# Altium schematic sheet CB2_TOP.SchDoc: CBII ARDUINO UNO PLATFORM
size A3; Engineer: SHOWELL; DocumentNumber: 1; Revision: 1.00; SheetNumber: 1; SheetTotal: 1; PageSetup: Record=PageOptions|CenterHorizontal=True|CenterVertical=True|PrintScale=1.47|XCorrection=1.00|YCorrection=1.00|PrintKind=0|BorderSize=5000000|LeftOffset=0|BottomOffset=0|Orientation=2|PaperLength=1000|PaperWidth=1000|Scale=100|PaperSource=7|PrintQuality=-4|MediaType=1|DitherType=10|PaperKind=A2|PrintScaleMode=1
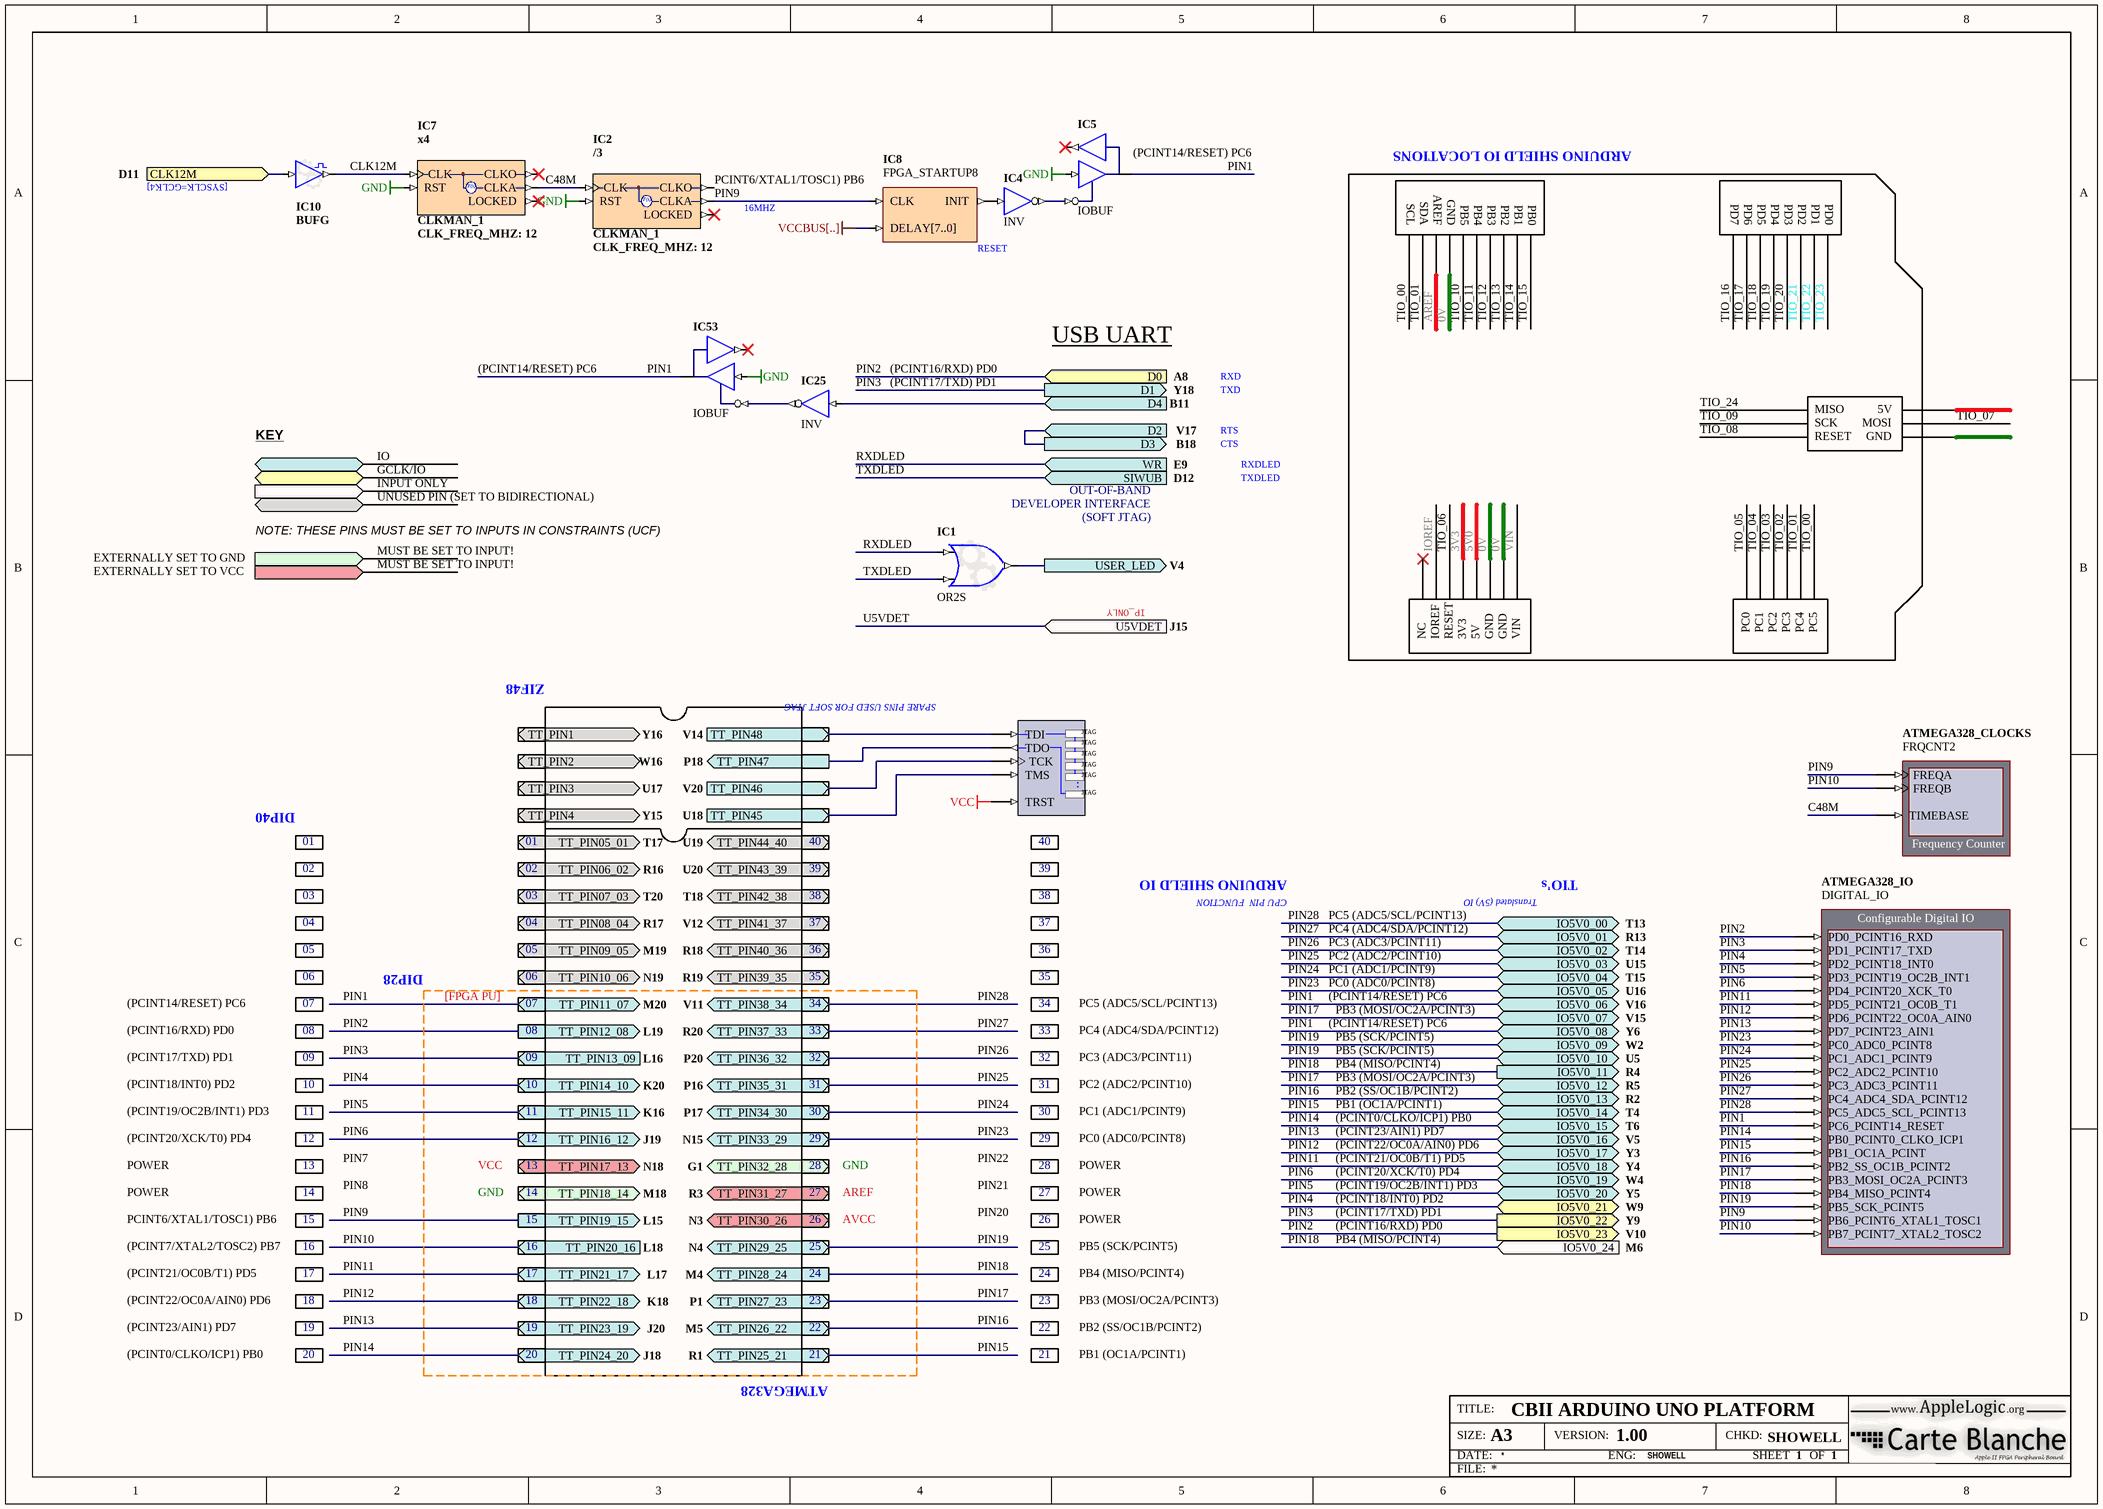
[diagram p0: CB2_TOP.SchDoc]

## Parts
ATMEGA328_CLOCKS  FRQCNT2
ATMEGA328_IO  DIGITAL_IO
IC1  OR2S
IC2  CLKMAN_1  CLK_FREQ_MHZ: 12  ClkA_Operation: /3
IC4  INV
IC5  IOBUF
IC7  CLKMAN_1  CLK_FREQ_MHZ: 12  ClkA_Operation: x4
IC8  FPGA_STARTUP8
IC10  BUFG
IC25  INV
IC53  IOBUF
NEXUS_JTAG_PORT  NEXUS_JTAG_PORT  (value not drawn)

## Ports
CLK12M (in, see D11), D0 (in, see A8), D1 (out, see Y18), D2 (in, see V17), D3 (out, see B18), D4 (in, see B11), IO5V0_00 (bidir, see T13), IO5V0_01 (bidir, see R13), IO5V0_02 (bidir, see T14), IO5V0_03 (bidir, see U15), IO5V0_04 (bidir, see T15), IO5V0_05 (bidir, see U16), IO5V0_06 (bidir, see V16), IO5V0_07 (bidir, see V15), IO5V0_08 (bidir, see Y6), IO5V0_09 (bidir, see W2), IO5V0_10 (bidir, see U5), IO5V0_11 (out, see R4), IO5V0_12 (bidir, see R5), IO5V0_13 (bidir, see R2), IO5V0_14 (bidir, see T4), IO5V0_15 (bidir, see T6), IO5V0_16 (bidir, see V5), IO5V0_17 (bidir, see Y3), IO5V0_18 (bidir, see Y4), IO5V0_19 (bidir, see W4), IO5V0_20 (bidir, see Y5), IO5V0_21 (bidir, see W9), IO5V0_22 (out, see Y9), IO5V0_23 (out, see V10), IO5V0_24 (in, see M6), SIWUB (in, see D12), TT_PIN1 (bidir, see Y16), TT_PIN2 (bidir, see W16), TT_PIN3 (bidir, see U17), TT_PIN4 (bidir, see Y15), TT_PIN05_01 (bidir, see T17), TT_PIN06_02 (bidir, see R16), TT_PIN07_03 (bidir, see T20), TT_PIN08_04 (bidir, see R17), TT_PIN09_05 (bidir, see M19), TT_PIN10_06 (bidir, see N19), TT_PIN11_07 (bidir, see M20), TT_PIN12_08 (out, see L19), TT_PIN13_09 (in, see L16), TT_PIN14_10 (bidir, see K20), TT_PIN15_11 (bidir, see K16), TT_PIN16_12 (bidir, see J19), TT_PIN17_13 (in, see N18), TT_PIN18_14 (in, see M18), TT_PIN19_15 (out, see L15), TT_PIN20_16 (in, see L18), TT_PIN21_17 (bidir, see L17), TT_PIN22_18 (bidir, see K18), TT_PIN23_19 (bidir, see J20), TT_PIN24_20 (bidir, see J18), TT_PIN25_21 (bidir, see R1), TT_PIN26_22 (bidir, see M5), TT_PIN27_23 (bidir, see P1), TT_PIN28_24 (out, see M4), TT_PIN29_25 (bidir, see N4), TT_PIN30_26 (in, see N3), TT_PIN31_27 (in, see R3), TT_PIN32_28 (in, see G1), TT_PIN33_29 (bidir, see N15), TT_PIN34_30 (bidir, see P17), TT_PIN35_31 (bidir, see P16), TT_PIN36_32 (bidir, see P20), TT_PIN37_33 (bidir, see R20), TT_PIN38_34 (bidir, see V11), TT_PIN39_35 (bidir, see R19), TT_PIN40_36 (bidir, see R18), TT_PIN41_37 (bidir, see V12), TT_PIN42_38 (bidir, see T18), TT_PIN43_39 (bidir, see U20), TT_PIN44_40 (bidir, see U19), TT_PIN45 (in, see U18), TT_PIN46 (in, see V20), TT_PIN47 (out, see P18), TT_PIN48 (in, see V14), U5VDET (in, see J15), USER_LED (out, see V4), WR (in, see E9)

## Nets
GND: IC2.RST IC5.I IC7.RST IC53.I
VCC: NEXUS_JTAG_PORT.TRST
C48M: ATMEGA328_CLOCKS.TIMEBASE IC2.CLK IC7.CLKA
CLK12M: IC7.CLK IC10.O
CLK12M: IC10.I ; port CLK12M  [a separate net that carries the same name]
D2: port D3, port D2
D4: IC25.I ; port D4
PIN1: ATMEGA328_IO.PC6_PCINT14_RESET IC5.IO IC53.IO ; port TT_PIN11_07, port IO5V0_06, port IO5V0_08
PIN2: ATMEGA328_IO.PD0_PCINT16_RXD ; port TT_PIN12_08, port IO5V0_23, port D0
PIN3: ATMEGA328_IO.PD1_PCINT17_TXD ; port TT_PIN13_09, port IO5V0_22, port D1
PIN4: ATMEGA328_IO.PD2_PCINT18_INT0 ; port TT_PIN14_10, port IO5V0_21
PIN5: ATMEGA328_IO.PD3_PCINT19_OC2B_INT1 ; port TT_PIN15_11, port IO5V0_20
PIN6: ATMEGA328_IO.PD4_PCINT20_XCK_T0 ; port TT_PIN16_12, port IO5V0_19
PIN9: ATMEGA328_CLOCKS.FREQA ATMEGA328_IO.PB6_PCINT6_XTAL1_TOSC1 IC2.CLKA IC8.CLK ; port TT_PIN19_15
PIN10: ATMEGA328_CLOCKS.FREQB ATMEGA328_IO.PB7_PCINT7_XTAL2_TOSC2 ; port TT_PIN20_16
PIN11: ATMEGA328_IO.PD5_PCINT21_OC0B_T1 ; port TT_PIN21_17, port IO5V0_18
PIN12: ATMEGA328_IO.PD6_PCINT22_OC0A_AIN0 ; port TT_PIN22_18, port IO5V0_17
PIN13: ATMEGA328_IO.PD7_PCINT23_AIN1 ; port TT_PIN23_19, port IO5V0_16
PIN14: ATMEGA328_IO.PB0_PCINT0_CLKO_ICP1 ; port TT_PIN24_20, port IO5V0_15
PIN15: ATMEGA328_IO.PB1_OC1A_PCINT ; port TT_PIN25_21, port IO5V0_14
PIN16: ATMEGA328_IO.PB2_SS_OC1B_PCINT2 ; port TT_PIN26_22, port IO5V0_13
PIN17: ATMEGA328_IO.PB3_MOSI_OC2A_PCINT3 ; port TT_PIN27_23, port IO5V0_12, port IO5V0_07
PIN18: ATMEGA328_IO.PB4_MISO_PCINT4 ; port TT_PIN28_24, port IO5V0_24, port IO5V0_11
PIN19: ATMEGA328_IO.PB5_SCK_PCINT5 ; port TT_PIN29_25, port IO5V0_10, port IO5V0_09
PIN23: ATMEGA328_IO.PC0_ADC0_PCINT8 ; port TT_PIN33_29, port IO5V0_05
PIN24: ATMEGA328_IO.PC1_ADC1_PCINT9 ; port TT_PIN34_30, port IO5V0_04
PIN25: ATMEGA328_IO.PC2_ADC2_PCINT10 ; port TT_PIN35_31, port IO5V0_03
PIN26: ATMEGA328_IO.PC3_ADC3_PCINT11 ; port TT_PIN36_32, port IO5V0_02
PIN27: ATMEGA328_IO.PC4_ADC4_SDA_PCINT12 ; port TT_PIN37_33, port IO5V0_01
PIN28: ATMEGA328_IO.PC5_ADC5_SCL_PCINT13 ; port TT_PIN38_34, port IO5V0_00
RXDLED: IC1.I0 ; port WR
TT_PIN45: NEXUS_JTAG_PORT.TMS ; port TT_PIN45
TT_PIN46: NEXUS_JTAG_PORT.TCK ; port TT_PIN46
TT_PIN47: NEXUS_JTAG_PORT.TDO ; port TT_PIN47
TT_PIN48: NEXUS_JTAG_PORT.TDI ; port TT_PIN48
TXDLED: IC1.I1 ; port SIWUB
USER_LED: IC1.O ; port USER_LED
NetIC4_I: IC4.I IC8.INIT
NetIC4_O: IC4.O IC5.T
NetIC25_O: IC25.O IC53.T

Not connected (* = marked no-connect by the designer): IC2 CLKO LOCKED*; IC5 O*; IC7 CLKO* LOCKED*; IC8 DELAY[7..0]; IC53 O*

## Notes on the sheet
- [SYSCLK=GCLK4]
- (near IC2) PCINT6/XTAL1/TOSC1) PB6
- (near IC5) (PCINT14/RESET) PC6
- ARDUINO SHIELD IO LOCATIONS
- (near IC2) 16MHZ
- SCL
- SDA
- AREF
- GND
- PB5
- PB4
- PB3
- PB2
- PB1
- PB0
- PD7
- PD6
- PD5
- PD4
- PD3
- PD2
- PD1
- PD0
- (near IC8) RESET
- (PCINT14/RESET) PC6
- (PCINT16/RXD) PD0
- USB UART
- RXD
- KEY
- (PCINT17/TXD) PD1
- TXD
- RTS
- CTS
- MISO
- SCK
- RESET
- MOSI
- 5V
- IO
- GCLK/IO
- INPUT ONLY
- UNUSED PIN (SET TO BIDIRECTIONAL)
- (near IC1) DEVELOPER INTERFACE
- OUT-OF-BAND
- RXDLED
- TXDLED
- EXTERNALLY SET TO GND
- EXTERNALLY SET TO VCC
- NOTE: THESE PINS MUST BE SET TO INPUTS IN CONSTRAINTS (UCF)
- MUST BE SET TO INPUT!
- (SOFT JTAG)
- IP_ONLY
- NC
- IOREF
- 3V3
- VIN
- PC0
- PC1
- PC2
- PC3
- PC4
- PC5
- ZIF48
- (near NEXUS_JTAG_PORT) SPARE PINS USED FOR SOFT JTAG
- DIP40
- 01
- 40
- (near NEXUS_JTAG_PORT) 40
- 02
- 03
- 39
- 38
- ARDUINO SHIELD IO
- CPU PIN  FUNCTION
- PC5 (ADC5/SCL/PCINT13)
- Translated (5V) IO
- TIO's
- 04
- 05
- 06
- DIP28
- 37
- 36
- 35
- PC4 (ADC4/SDA/PCINT12)
- PC3 (ADC3/PCINT11)
- PC2 (ADC2/PCINT10)
- PC1 (ADC1/PCINT9)
- PC0 (ADC0/PCINT8)
- 07
- 08
- [FPGA PU]
- 34
- 33
- PB5 (SCK/PCINT5)
- PB3 (MOSI/OC2A/PCINT3)
- (PCINT18/INT0) PD2
- (PCINT19/OC2B/INT1) PD3
- 09
- 10
- 11
- 32
- 31
- 30
- (PCINT0/CLKO/ICP1) PB0
- PB4 (MISO/PCINT4)
- PB2 (SS/OC1B/PCINT2)
- PB1 (OC1A/PCINT1)
- (PCINT20/XCK/T0) PD4
- POWER
- 12
- 13
- VCC
- 29
- 28
- (PCINT21/OC0B/T1) PD5
- (PCINT22/OC0A/AIN0) PD6
- (PCINT23/AIN1) PD7
- PCINT6/XTAL1/TOSC1) PB6
- (PCINT7/XTAL2/TOSC2) PB7
- 14
- 15
- 16
- 27
- 26
- 25
- AVCC
- 17
- 18
- 24
- 23
- 19
- 20
- 22
- 21
- ATMEGA328
- Labels drawn without touching a wire or pin: 0V, 3V3, 5V0, AREF, IOREF, PIN7, PIN8, PIN20, PIN21, PIN22, TIO_00, TIO_01, TIO_02, TIO_03, TIO_04, TIO_05, TIO_06, TIO_07, TIO_08, TIO_09, TIO_10, TIO_11, TIO_12, TIO_13, TIO_14, TIO_15, TIO_16, TIO_17, TIO_18, TIO_19, TIO_20, TIO_21, TIO_22, TIO_23, TIO_24, VCCBUS[..], VIN

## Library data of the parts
ATMEGA328_CLOCKS = FRQCNT2: Frequency Counter; NEXUS_CORE: Instrument; NEXUS_JTAG_DEVICE: True; NEXUS_JTAG_ORDER: 0
ATMEGA328_IO = DIGITAL_IO: Configurable Digital IO; NEXUS_CORE: Instrument; NEXUS_JTAG_DEVICE: True; NEXUS_JTAG_ORDER: 0; ConfigurationParameters: {}Version[2.0]{}StorageType[3]{}InterfaceType[Parallel]{}SchCompWidth[140]{}Input0Name[PD0_PCINT16_RXD]{}Input0Width[1]{}Input0InitValue[0]{}Input0Kind[LEDs]{}Input0LEDStyle[Green]{}Input1Name[PD1_PCINT17_TXD]{}Input1Width[1]{}Input1InitValue[0]{}Input1Kind[LEDs]{}Input1LEDStyle[Green]{}Input2Name[PD2_PCINT18_INT0]{}Input2Width[1]{}Input2InitValue[0]{}Input2Kind[LEDs]{}Input2LEDStyle[Green]{}Input3Name[PD3_PCINT19_OC2B_INT1]{}Input3Width[1]{}Input3InitValue[0]{}Input3Kind[LEDs]{}Input3LEDStyle[Green]{}Input4Name[PD4_PCINT20_XCK_T0]{}Input4Width[1]{}Input4InitValue[0]{}Input4Kind[LEDs]{}Input4LEDStyle[Green]{}Input5Name[PD5_PCINT21_OC0B_T1]{}Input5Width[1]{}Input5InitValue[0]{}Input5Kind[LEDs]{}Input5LEDStyle[Green]{}Input6Name[PD6_PCINT22_OC0A_AIN0]{}Input6Width[1]{}Input6InitValue[0]{}Input6Kind[LEDs]{}Input6LEDStyle[Green]{}Input7Name[PD7_PCINT23_AIN1]{}Input7Width[1]{}Input7InitValue[0]{}Input7Kind[LEDs]{}Input7LEDStyle[Green]{}Input8Name[PC0_ADC0_PCINT8]{}Input8Width[1]{}Input8InitValue[0]{}Input8Kind[LEDs]{}Input8LEDStyle[Red]{}Input9Name[PC1_ADC1_PCINT9]{}Input9Width[1]{}Input9InitValue[0]{}Input9Kind[LEDs]{}Input9LEDStyle[Red]{}Input10Name[PC2_ADC2_PCINT10]{}Input10Width[1]{}Input10InitValue[0]{}Input10Kind[LEDs]{}Input10LEDStyle[Red]{}Input11Name[PC3_ADC3_PCINT11]{}Input11Width[1]{}Input11InitValue[0]{}Input11Kind[LEDs]{}Input11LEDStyle[Red]{}Input12Name[PC4_ADC4_SDA_PCINT12]{}Input12Width[1]{}Input12InitValue[0]{}Input12Kind[LEDs]{}Input12LEDStyle[Red]{}Input13Name[PC5_ADC5_SCL_PCINT13]{}Input13Width[1]{}Input13InitValue[0]{}Input13Kind[LEDs]{}Input13LEDStyle[Red]{}Input14Name[PC6_PCINT14_RESET]{}Input14Width[1]{}Input14InitValue[0]{}Input14Kind[LEDs]{}Input14LEDStyle[Red]{}Input15Name[PB0_PCINT0_CLKO_ICP1]{}Input15Width[1]{}Input15InitValue[0]{}Input15Kind[LEDs]{}Input15LEDStyle[Blue]{}Input16Name[PB1_OC1A_PCINT]{}Input16Width[1]{}Input16InitValue[0]{}Input16Kind[LEDs]{}Input16LEDStyle[Blue]{}Input17Name[PB2_SS_OC1B_PCINT2]{}Input17Width[1]{}Input17InitValue[0]{}Input17Kind[LEDs]{}Input17LEDStyle[Blue]{}Input18Name[PB3_MOSI_OC2A_PCINT3]{}Input18Width[1]{}Input18InitValue[0]{}Input18Kind[LEDs]{}Input18LEDStyle[Blue]{}Input19Name[PB4_MISO_PCINT4]{}Input19Width[1]{}Input19InitValue[0]{}Input19Kind[LEDs]{}Input19LEDStyle[Blue]{}Input20Name[PB5_SCK_PCINT5]{}Input20Width[1]{}Input20InitValue[0]{}Input20Kind[LEDs]{}Input20LEDStyle[Blue]{}Input21Name[PB6_PCINT6_XTAL1_TOSC1]{}Input21Width[1]{}Input21InitValue[0]{}Input21Kind[LEDs]{}Input21LEDStyle[Blue]{}Input22Name[PB7_PCINT7_XTAL2_TOSC2]{}Input22Width[1]{}Input22InitValue[0]{}Input22Kind[LEDs]{}Input22LEDStyle[Blue]{}NoOutputs[ ]{}Designator[ATMEGA328_IO]{}InternalID[1]{}
IC1 = GATE: Configurable Generic Gate; ConfiguratorName: GENERIC_GATE; ConfigurationParameters: {}Version[1.1]{}GateKind[OR]{}BusInput[False]{}GateInputType[Bit]{}GateOutputOption[Normal]{}BusWidth[8]{}RegisterOutputs[False]{}NegativeClockEdge[False]{}InputCount[2]{}InputInvert0[False]{}InputInvert1[False]{}
IC2 IC7 = CLKMAN_1: Single Operational Output Clock Manager; Clk_Count: 1
IC4 IC25 = INV: Inverter; FunctionalClass: Logic Primitive; ArchiveName: GENERIC; VHDLIB_SIM: GENERIC_LIB
IC5 IC53 = IOBUF: Input/Output Buffer; Enable: Low; Control: Common Control T; ArchiveName: GENERIC; VHDLIB_SIM: GENERIC_LIB
IC8 = FPGA_STARTUP8: FPGA Startup With 8 Bit Delay
IC10 = BUFG: Configurable Global Clock Buffer; ConfiguratorName: GENERIC_BUFFER; ConfigurationParameters: {}Version[1.1]{}SignalCount[1]{}SignalWidth0[1]{}OutputOption0[Global Clock]{}EnableMode[None]{}ShowPinNames[False]{}
NEXUS_JTAG_PORT = NEXUS_JTAG_PORT: Soft Nexus-Chain Connector; NEXUS_JTAG_CONNECTOR: True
